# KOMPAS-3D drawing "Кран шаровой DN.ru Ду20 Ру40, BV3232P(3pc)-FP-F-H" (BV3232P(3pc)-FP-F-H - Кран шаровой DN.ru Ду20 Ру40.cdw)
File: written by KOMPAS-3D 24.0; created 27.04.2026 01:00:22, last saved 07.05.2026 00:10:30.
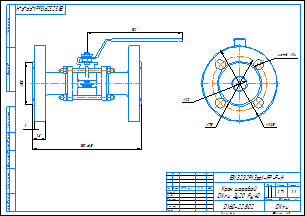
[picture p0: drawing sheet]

Document properties: Автор: Максим; Форматы листов документа: A3; Полное имя файла: BVxxP(3pc)-FP-F-H - Кран шаровой DN.ru Ду20 Ру40.cdw; Масса: 2.71; Наименование: Кран шаровой DN.ru Ду20 Ру40; Количество листов документа: 1; Примечание: D160-22802

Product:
- Body: Тело 1  | qty 1
    Масса: 2.799739
- Part/product: Кран шаровой DN.ru Ду20 Ру40  | designation BV3232P(3pc)-FP-F-H
    Масса: 2.71
    Раздел спецификации: Прочие изделия
    Форматы листов документа: A3
    Примечание: D160-22802

Views: Вид 1, Вид:2, Проекционный вид 2, Вид:1
Referenced files in D:\Rabota ebanaya\Апрель\BVxxP(3pc)-FP-F-H Кран шаровой Ду15-100\Исходники\DN20\: BVxxP(3pc)-FP-F-H - Кран шаровой DN.ru Ду20 Ру40.m3d, BVxxP(3pc)-FP-F-H - Кран шаровой DN.ru Ду20 Ру40.cdw
Referenced files in D:\Rabota ebanaya\Апрель\BV3232P(3pc)-FP-F-H Кран шаровой Ду15-100\Исходники\DN20\: BV3232P(3pc)-FP-F-H - Кран шаровой DN.ru Ду20 Ру40.m3d
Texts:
  Линейный размер
  BV3232P(3pc)-FP-F-H
  Диаметральный размер
  Кран шаровой
  DN.ru Ду20 Ру40
  Кран шаровой DN.ru Ду20 Ру40
  BV3232P(3pc)-FP-F-H Кран шаровой DN.ru Ду20 Ру40
Dimensions and other numbers on the sheet: 0; 3; 2; 4; 132; 150±1,5; 58; 18; 20; 105; 75; 4 отв.; 14; 1:1; 1; 2,71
